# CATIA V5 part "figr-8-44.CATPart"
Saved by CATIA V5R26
Part number: Part1
Bounding box of the stored display mesh (mm): x -50 to 50, y -50 to 50, z 0 to 25
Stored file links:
  D:\_Deepak\CATIA\CATIA V5-6R2016_Deepak\Resources\Part files\Partfiles\c08_catia_v5_6r2016_prt\figr-8-44.CATPart
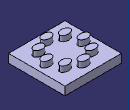
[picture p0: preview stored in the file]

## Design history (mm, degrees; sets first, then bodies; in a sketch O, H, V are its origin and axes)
Body1 (main body)
  Sketch1 on xy-plane, origin (0, 0, 0), H (1, 0, 0), V (0, 1, 0)
    line L1 (-50, 50) -> (50, 50)
    line L2 (50, 50) -> (50, -50)
    line L3 (50, -50) -> (-50, -50)
    line L4 (-50, -50) -> (-50, 50)
    axis line L5 (50, -50) -> (-50, 50)
    length L2 = 100
    length L3 = 100
    horizontal: L1 H, L3 H
    vertical: L2 V, L4 V
    midpoint: L5 O
  Pad1: profile Sketch1, direction (0, 0, 1), length 15
  Sketch2 on face of Pad1, origin (0, 0, 15), H (1, 0, 0), V (0, 1, 0)
    point P1 (0, -32.9864)
    ellipse A1 centre (0, -32.9864) semi-axes 9.9006, 6.5465 rotation 0
    point P2 (0, -26.4399)
    coincidence: P1 V, P2 V, A1 P2
  Pad2: profile Sketch2, direction (0, 0, 1), length 10
  CircPattern1: of Pad2, instances 8, angular step 45 {= 360.0*1 deg/CircPattern1.AngularNumber}, axis from edge of Sketch3
  Sketch3 on yz-plane, origin (0, 0, 0), H (0, 1, 0), V (0, 0, 1)
    line L1 (0, 0) -> (0, 18.4864)
    vertical: L1 V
